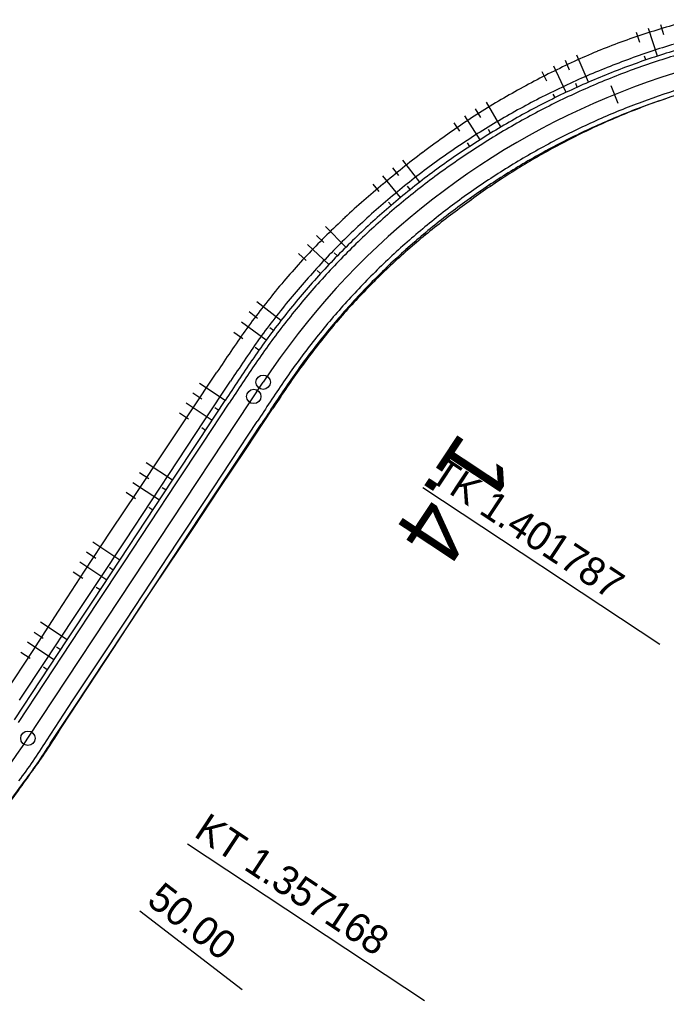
# Model space of a CAD drawing. Extents: x -481645 to -478728, y -1113199 to -1110710.
# Drawn here: x -478987.9 to -478920.3, y -1110817.8 to -1110715.2 of the extents above; entities that cross this region are included whole.
import ezdxf

# ---------------------------------------------------------------- set-up
doc = ezdxf.new("R2010")
doc.units = 0
for name, color, linetype in [('CP14_HATCH_SLOPE_L', 7, 'Continuous'), ('CP1_HECTOMETRY', 7, 'Continuous'), ('O6_HATCH_SLOPE_L', 7, 'Continuous'), ('O6_HATCH_SLOPE_R', 7, 'Continuous'), ('O6_HECTOMETRY', 7, 'Continuous'), ('O6_HLBODY', 7, 'Continuous'), ('O6_HRANA_TELESO', 7, 'Continuous'), ('O6_OSA', 7, 'Continuous'), ('O6_VOZOVKA', 7, 'Continuous'), ('O6_ZPEVKRAJ', 7, 'Continuous')]:
    doc.layers.add(name, color=color, linetype=linetype)

msp = doc.modelspace()

# ---------------------------------------------------------------- linework, layer by layer
at = {"layer": 'CP14_HATCH_SLOPE_L'}
for p, q in [((-478921.45, -1110723.87), (-478921.45, -1110723.88)), ((-478921.44, -1110723.89), (-478921.44, -1110723.89)), ((-478920.3, -1110723.48), (-478920.29, -1110723.49)), ((-478923.73, -1110724.71), (-478923.72, -1110724.73)), ((-478923.72, -1110724.74), (-478923.72, -1110724.74)), ((-478922.59, -1110724.28), (-478922.58, -1110724.3)), ((-478929.3, -1110727.12), (-478929.27, -1110727.19)), ((-478931.48, -1110728.2), (-478931.43, -1110728.29)), ((-478930.39, -1110727.65), (-478930.38, -1110727.69)), ((-478930.36, -1110727.73), (-478930.36, -1110727.73)), ((-478932.55, -1110728.77), (-478932.53, -1110728.82)), ((-478932.5, -1110728.86), (-478932.5, -1110728.86)), ((-478937.78, -1110731.85), (-478937.69, -1110731.99)), ((-478939.8, -1110733.2), (-478939.7, -1110733.36)), ((-478938.8, -1110732.52), (-478938.75, -1110732.59)), ((-478938.7, -1110732.67), (-478938.7, -1110732.67)), ((-478940.8, -1110733.9), (-478940.74, -1110733.98)), ((-478940.68, -1110734.06), (-478940.68, -1110734.06)), ((-478946.53, -1110738.4), (-478946.48, -1110738.46)), ((-478946.42, -1110738.53), (-478946.42, -1110738.53)), ((-478945.61, -1110737.61), (-478945.49, -1110737.75)), ((-478947.45, -1110739.2), (-478947.34, -1110739.32)), ((-478948.35, -1110740.01), (-478948.29, -1110740.07)), ((-478948.24, -1110740.13), (-478948.24, -1110740.13)), ((-478952.65, -1110744.29), (-478952.57, -1110744.37)), ((-478953.47, -1110745.19), (-478953.43, -1110745.23)), ((-478953.39, -1110745.27), (-478953.39, -1110745.27)), ((-478954.28, -1110746.1), (-478954.19, -1110746.17)), ((-478955.07, -1110747.02), (-478955.03, -1110747.06)), ((-478954.99, -1110747.09), (-478954.99, -1110747.09)), ((-478958.81, -1110751.81), (-478958.72, -1110751.87)), ((-478959.51, -1110752.8), (-478959.47, -1110752.83)), ((-478959.42, -1110752.86), (-478959.42, -1110752.86)), ((-478960.2, -1110753.8), (-478960.11, -1110753.86)), ((-478960.88, -1110754.82), (-478960.83, -1110754.85)), ((-478960.79, -1110754.88), (-478960.79, -1110754.88)), ((-478964.32, -1110760.04), (-478964.25, -1110760.09)), ((-478965.01, -1110761.08), (-478964.98, -1110761.11)), ((-478965.7, -1110762.12), (-478965.63, -1110762.17)), ((-478964.94, -1110761.13), (-478964.94, -1110761.13)), ((-478966.39, -1110763.17), (-478966.36, -1110763.19)), ((-478966.32, -1110763.21), (-478966.32, -1110763.21)), ((-478969.84, -1110768.38), (-478969.79, -1110768.42)), ((-478970.53, -1110769.43), (-478970.5, -1110769.44)), ((-478970.48, -1110769.45), (-478970.48, -1110769.45)), ((-478971.21, -1110770.47), (-478971.18, -1110770.49)), ((-478971.9, -1110771.51), (-478971.89, -1110771.52)), ((-478971.87, -1110771.53), (-478971.87, -1110771.53)), ((-478975.35, -1110776.73), (-478975.34, -1110776.73)), ((-478976.04, -1110777.77), (-478976.03, -1110777.77)), ((-478976.03, -1110777.77), (-478976.03, -1110777.77)), ((-478976.73, -1110778.81), (-478976.71, -1110778.82)), ((-478977.42, -1110779.85), (-478977.41, -1110779.86)), ((-478977.4, -1110779.86), (-478977.4, -1110779.86)), ((-478980.86, -1110785.07), (-478980.83, -1110785.09)), ((-478981.55, -1110786.11), (-478981.53, -1110786.12)), ((-478981.52, -1110786.13), (-478981.52, -1110786.13)), ((-478982.24, -1110787.16), (-478982.2, -1110787.18)), ((-478982.93, -1110788.2), (-478982.91, -1110788.21)), ((-478982.89, -1110788.22), (-478982.89, -1110788.22)), ((-478986.42, -1110793.44), (-478986.37, -1110793.47)), ((-478987.16, -1110794.49), (-478987.13, -1110794.5)), ((-478987.11, -1110794.52), (-478987.11, -1110794.52)), ((-478987.9, -1110795.52), (-478987.85, -1110795.56))]:
    msp.add_line(p, q, dxfattribs=at)
at = {"layer": 'CP1_HECTOMETRY'}
msp.add_line((-478987.06, -1110790.36), (-478962.46, -1110753.14), dxfattribs=at)
for centre, radius, start, end in [((-478895.71, -1110797.24), 80, 76.6017, 146.545), ((-479070.49, -1110735.23), 100, 317.0793, 326.545)]:
    msp.add_arc(centre, radius, start, end, dxfattribs=at)
at = {"layer": 'O6_HATCH_SLOPE_L'}
msp.add_circle((-478963.44, -1110754.63), 0.75, dxfattribs=at)
at = {"layer": 'O6_HATCH_SLOPE_R'}
for p, q in [((-478920.56, -1110716.84), (-478920.89, -1110715.79)), ((-478923.07, -1110717.64), (-478923.43, -1110716.58)), ((-478921.23, -1110719.05), (-478922.16, -1110716.18)), ((-478928.43, -1110721.78), (-478929.65, -1110718.97)), ((-478922.44, -1110719.45), (-478922.58, -1110719.07)), ((-478930.78, -1110722.84), (-478932.07, -1110720.09)), ((-478930.41, -1110720.53), (-478930.86, -1110719.52)), ((-478932.78, -1110721.66), (-478933.27, -1110720.68)), ((-478929.61, -1110722.3), (-478929.78, -1110721.92)), ((-478931.93, -1110723.39), (-478932.12, -1110723.02)), ((-478937.59, -1110726.45), (-478939.1, -1110723.88)), ((-478939.69, -1110725.48), (-478940.24, -1110724.58)), ((-478941.9, -1110726.89), (-478942.47, -1110726.02)), ((-478939.78, -1110727.79), (-478941.36, -1110725.29)), ((-478938.69, -1110727.11), (-478938.91, -1110726.74)), ((-478940.86, -1110728.49), (-478941.1, -1110728.12)), ((-478946.09, -1110732.22), (-478947.86, -1110729.92)), ((-478948.28, -1110731.53), (-478948.91, -1110730.74)), ((-478948.09, -1110733.82), (-478949.95, -1110731.58)), ((-478950.32, -1110733.2), (-478950.97, -1110732.43)), ((-478947.1, -1110733.01), (-478947.37, -1110732.66)), ((-478949.08, -1110734.65), (-478949.37, -1110734.31)), ((-478953.8, -1110739.01), (-478955.94, -1110736.86)), ((-478956.13, -1110738.54), (-478956.89, -1110737.79)), ((-478955.59, -1110740.85), (-478957.83, -1110738.74)), ((-478957.95, -1110740.43), (-478958.76, -1110739.7)), ((-478954.7, -1110739.92), (-478955.03, -1110739.6)), ((-478956.46, -1110741.79), (-478956.81, -1110741.48)), ((-478960.61, -1110746.7), (-478963.11, -1110744.75)), ((-478963.04, -1110746.48), (-478963.93, -1110745.8)), ((-478962.15, -1110748.75), (-478964.73, -1110746.87)), ((-478961.39, -1110747.72), (-478961.77, -1110747.44)), ((-478964.6, -1110748.6), (-478965.52, -1110747.95)), ((-478962.9, -1110749.8), (-478963.29, -1110749.52)), ((-478966.42, -1110755.05), (-478969.12, -1110753.26)), ((-478968.87, -1110754.93), (-478969.82, -1110754.3)), ((-478967.8, -1110757.14), (-478970.51, -1110755.34)), ((-478967.11, -1110756.09), (-478967.51, -1110755.82)), ((-478970.25, -1110757.01), (-478971.21, -1110756.38)), ((-478968.49, -1110758.18), (-478968.89, -1110757.91)), ((-478971.93, -1110763.39), (-478974.69, -1110761.57)), ((-478974.41, -1110763.25), (-478975.39, -1110762.61)), ((-478973.31, -1110765.48), (-478976.08, -1110763.65)), ((-478972.62, -1110764.44), (-478973.03, -1110764.17)), ((-478975.8, -1110765.33), (-478976.78, -1110764.68)), ((-478974, -1110766.52), (-478974.41, -1110766.25)), ((-478977.44, -1110771.74), (-478980.26, -1110769.87)), ((-478979.95, -1110771.58), (-478980.95, -1110770.92)), ((-478978.82, -1110773.82), (-478981.64, -1110771.96)), ((-478981.33, -1110773.66), (-478982.32, -1110773.01)), ((-478978.13, -1110772.78), (-478978.54, -1110772.51)), ((-478979.51, -1110774.86), (-478979.92, -1110774.59)), ((-478982.96, -1110780.08), (-478985.74, -1110778.24)), ((-478985.45, -1110779.93), (-478986.42, -1110779.29)), ((-478984.34, -1110782.16), (-478987.11, -1110780.33)), ((-478986.82, -1110782.02), (-478987.79, -1110781.38)), ((-478983.65, -1110781.12), (-478984.06, -1110780.85)), ((-478985.03, -1110783.21), (-478985.44, -1110782.93))]:
    msp.add_line(p, q, dxfattribs=at)
at = {"layer": 'O6_HECTOMETRY'}
for p, q in [((-478945.77, -1110764.16), (-478920.99, -1110780.53)), ((-478970.37, -1110801.39), (-478945.59, -1110817.76))]:
    msp.add_line(p, q, dxfattribs=at)
for centre in [(-478962.46, -1110753.14), (-478987.06, -1110790.36)]:
    msp.add_circle(centre, 0.75, dxfattribs=at)
at = {"layer": 'O6_HLBODY'}
for p, q in [((-478925.33, -1110724), (-478926.08, -1110722.15)), ((-478975.36, -1110808.39), (-478964.66, -1110816.62))]:
    msp.add_line(p, q, dxfattribs=at)
at = {"layer": 'O6_HRANA_TELESO'}
for p, q in [((-478968.63, -1110757.19), (-478965.88, -1110753.02)), ((-478971.39, -1110761.36), (-478968.63, -1110757.19)), ((-478974.15, -1110765.53), (-478971.39, -1110761.36)), ((-478976.9, -1110769.71), (-478974.15, -1110765.53)), ((-478979.66, -1110773.88), (-478976.9, -1110769.71)), ((-478982.42, -1110778.05), (-478979.66, -1110773.88)), ((-478985.17, -1110782.22), (-478982.42, -1110778.05)), ((-478987.93, -1110786.39), (-478985.17, -1110782.22))]:
    msp.add_line(p, q, dxfattribs=at)
for centre, radius, start, end in [((-478895.71, -1110797.24), 82.92, 104.8528, 108.4338), ((-478895.71, -1110797.24), 82.92, 108.4338, 112.0148), ((-478895.71, -1110797.24), 82.92, 112.0148, 115.5957), ((-478895.71, -1110797.24), 82.92, 115.5957, 119.1767), ((-478895.71, -1110797.24), 82.92, 119.1767, 122.7577), ((-478895.71, -1110797.24), 82.92, 122.7577, 126.3387), ((-478895.71, -1110797.24), 82.92, 126.3387, 129.9197), ((-478895.71, -1110797.24), 82.92, 129.9197, 133.5007), ((-478895.71, -1110797.24), 82.92, 133.5007, 137.0817), ((-478895.71, -1110797.24), 82.92, 137.0817, 140.6626), ((-478895.71, -1110797.24), 82.92, 140.6626, 144.2436), ((-478758.72, -1110890.73), 248.75, 145.2068, 146.3854)]:
    msp.add_arc(centre, radius, start, end, dxfattribs=at)
at = {"layer": 'O6_OSA'}
for p, q in [((-478970.06, -1110756.25), (-478967.29, -1110752.08)), ((-478964.25, -1110760.09), (-478961.48, -1110755.92)), ((-478972.84, -1110760.41), (-478970.06, -1110756.25)), ((-478967.02, -1110764.25), (-478964.25, -1110760.09)), ((-478975.61, -1110764.56), (-478972.84, -1110760.41)), ((-478978.39, -1110768.72), (-478975.61, -1110764.56)), ((-478969.79, -1110768.42), (-478967.02, -1110764.25)), ((-478981.15, -1110772.89), (-478978.39, -1110768.72)), ((-478972.57, -1110772.57), (-478969.79, -1110768.42)), ((-478983.87, -1110777.09), (-478981.15, -1110772.89)), ((-478975.34, -1110776.73), (-478972.57, -1110772.57)), ((-478986.59, -1110781.28), (-478983.87, -1110777.09)), ((-478978.09, -1110780.91), (-478975.34, -1110776.73)), ((-478989.32, -1110785.48), (-478986.59, -1110781.28)), ((-478980.83, -1110785.09), (-478978.09, -1110780.91)), ((-478983.58, -1110789.27), (-478980.83, -1110785.09))]:
    msp.add_line(p, q, dxfattribs=at)
for centre, radius, start, end in [((-478896.21, -1110797.39), 84.85, 104.504, 108.0851), ((-478895.81, -1110797.27), 84.87, 108.3674, 111.9484), ((-478894.52, -1110796.7), 84.83, 112.897, 116.4784), ((-478894.53, -1110796.61), 84.75, 116.5022, 120.0836), ((-478894.54, -1110796.52), 84.67, 120.1042, 123.6856), ((-478895.32, -1110797.09), 77.73, 108.7397, 112.3208), ((-478895.17, -1110797), 77.7, 112.4513, 116.0324), ((-478894.55, -1110796.43), 84.58, 123.7165, 127.298), ((-478895.07, -1110796.9), 77.65, 116.1284, 119.7096), ((-478894.99, -1110796.67), 84.51, 126.9602, 130.5414), ((-478895.07, -1110796.85), 77.61, 119.73, 123.3111), ((-478895.07, -1110796.79), 77.56, 123.3359, 126.917), ((-478896.37, -1110797.82), 84.51, 129.3279, 132.9091), ((-478896.14, -1110797.57), 77.55, 125.9385, 129.5196), ((-478896.39, -1110797.92), 84.56, 132.8479, 136.4291), ((-478896.11, -1110797.59), 77.59, 129.5275, 133.1086), ((-478895.92, -1110797.47), 84.6, 136.8741, 140.4551), ((-478896.08, -1110797.6), 77.62, 133.1216, 136.7027), ((-478895.76, -1110797.3), 84.61, 140.6128, 144.1938), ((-478895.8, -1110797.33), 77.64, 136.9881, 140.5691), ((-478755.88, -1110892.6), 253.85, 145.2193, 146.3896), ((-478895.71, -1110797.24), 77.64, 140.666, 144.247), ((-478767.54, -1110884.93), 232.93, 145.1618, 146.3683), ((-479027.52, -1110763.08), 51.15, 323.5502, 329.2088), ((-479070.67, -1110735.48), 102.31, 322.6103, 325.4751)]:
    msp.add_arc(centre, radius, start, end, dxfattribs=at)
at = {"layer": 'O6_VOZOVKA'}
for p, q in [((-478968.76, -1110759.5), (-478966, -1110755.32)), ((-478965.84, -1110761.43), (-478963.08, -1110757.25)), ((-478971.51, -1110763.67), (-478968.76, -1110759.5)), ((-478968.59, -1110765.6), (-478965.84, -1110761.43)), ((-478974.27, -1110767.84), (-478971.51, -1110763.67)), ((-478971.35, -1110769.77), (-478968.59, -1110765.6)), ((-478977.03, -1110772.01), (-478974.27, -1110767.84)), ((-478974.11, -1110773.94), (-478971.35, -1110769.77)), ((-478979.78, -1110776.18), (-478977.03, -1110772.01)), ((-478976.86, -1110778.11), (-478974.11, -1110773.94)), ((-478982.54, -1110780.35), (-478979.78, -1110776.18)), ((-478979.62, -1110782.28), (-478976.86, -1110778.11)), ((-478985.3, -1110784.53), (-478982.54, -1110780.35)), ((-478982.38, -1110786.46), (-478979.62, -1110782.28)), ((-478988.05, -1110788.7), (-478985.3, -1110784.53)), ((-478985.13, -1110790.63), (-478982.38, -1110786.46))]:
    msp.add_line(p, q, dxfattribs=at)
for centre, radius, start, end in [((-478895.71, -1110797.24), 81.75, 106.2794, 109.8604), ((-478895.71, -1110797.24), 81.75, 109.8604, 113.4414), ((-478895.71, -1110797.24), 78.25, 106.2794, 109.8604), ((-478895.71, -1110797.24), 81.75, 113.4414, 117.0224), ((-478895.71, -1110797.24), 78.25, 109.8604, 113.4414), ((-478895.71, -1110797.24), 81.75, 117.0224, 120.6034), ((-478895.71, -1110797.24), 78.25, 113.4414, 117.0224), ((-478895.71, -1110797.24), 81.75, 120.6034, 124.1843), ((-478895.71, -1110797.24), 78.25, 117.0224, 120.6034), ((-478895.71, -1110797.24), 81.75, 124.1843, 127.7653), ((-478895.71, -1110797.24), 78.25, 120.6034, 124.1843), ((-478895.71, -1110797.24), 81.75, 127.7653, 131.3463), ((-478895.71, -1110797.24), 78.25, 124.1843, 127.7653), ((-478895.71, -1110797.24), 78.25, 127.7653, 131.3463), ((-478895.71, -1110797.24), 81.75, 131.3463, 134.9273), ((-478895.71, -1110797.24), 78.25, 131.3463, 134.9273), ((-478895.71, -1110797.24), 81.75, 134.9273, 138.5083), ((-478895.71, -1110797.24), 78.25, 134.9273, 138.5083), ((-478895.71, -1110797.24), 81.75, 138.5083, 142.0893), ((-478895.71, -1110797.24), 78.25, 138.5083, 142.0893), ((-478895.71, -1110797.24), 81.75, 142.0893, 145.6703), ((-478895.71, -1110797.24), 78.25, 142.0893, 145.6703), ((-478760.26, -1110888.81), 245.25, 145.8492, 147.0236), ((-478766.1, -1110884.95), 234.75, 145.833, 147.0468), ((-479028.47, -1110763.97), 50.88, 322.693, 328.4079)]:
    msp.add_arc(centre, radius, start, end, dxfattribs=at)
at = {"layer": 'O6_ZPEVKRAJ'}
for p, q in [((-478969.17, -1110759.22), (-478966.42, -1110755.05)), ((-478965.42, -1110761.7), (-478962.66, -1110757.53)), ((-478971.93, -1110763.39), (-478969.17, -1110759.22)), ((-478968.18, -1110765.87), (-478965.42, -1110761.7)), ((-478974.69, -1110767.56), (-478971.93, -1110763.39)), ((-478970.93, -1110770.04), (-478968.18, -1110765.87)), ((-478977.44, -1110771.74), (-478974.69, -1110767.56)), ((-478973.69, -1110774.22), (-478970.93, -1110770.04)), ((-478980.2, -1110775.91), (-478977.44, -1110771.74)), ((-478976.45, -1110778.39), (-478973.69, -1110774.22)), ((-478982.96, -1110780.08), (-478980.2, -1110775.91)), ((-478979.2, -1110782.56), (-478976.45, -1110778.39)), ((-478985.71, -1110784.25), (-478982.96, -1110780.08)), ((-478981.96, -1110786.73), (-478979.2, -1110782.56)), ((-478988.47, -1110788.42), (-478985.71, -1110784.25)), ((-478984.72, -1110790.9), (-478981.96, -1110786.73))]:
    msp.add_line(p, q, dxfattribs=at)
for centre, radius, start, end in [((-478895.71, -1110797.24), 82.25, 106.2794, 109.8604), ((-478895.71, -1110797.24), 82.25, 109.8604, 113.4414), ((-478895.71, -1110797.24), 82.25, 113.4414, 117.0224), ((-478895.71, -1110797.24), 77.75, 106.2794, 109.8604), ((-478895.71, -1110797.24), 82.25, 117.0224, 120.6034), ((-478895.71, -1110797.24), 77.75, 109.8604, 113.4414), ((-478895.71, -1110797.24), 77.75, 113.4414, 117.0224), ((-478895.71, -1110797.24), 82.25, 120.6034, 124.1843), ((-478895.71, -1110797.24), 77.75, 117.0224, 120.6034), ((-478895.71, -1110797.24), 82.25, 124.1843, 127.7653), ((-478895.71, -1110797.24), 77.75, 120.6034, 124.1843), ((-478895.71, -1110797.24), 82.25, 127.7653, 131.3463), ((-478895.71, -1110797.24), 77.75, 124.1843, 127.7653), ((-478895.71, -1110797.24), 82.25, 131.3463, 134.9273), ((-478895.71, -1110797.24), 77.75, 127.7653, 131.3463), ((-478895.71, -1110797.24), 82.25, 134.9273, 138.5083), ((-478895.71, -1110797.24), 77.75, 131.3463, 134.9273), ((-478895.71, -1110797.24), 77.75, 134.9273, 138.5083), ((-478895.71, -1110797.24), 82.25, 138.5083, 142.0893), ((-478895.71, -1110797.24), 77.75, 138.5083, 142.0893), ((-478895.71, -1110797.24), 82.25, 142.0893, 145.6703), ((-478895.71, -1110797.24), 77.75, 142.0893, 145.6703), ((-478759.43, -1110889.36), 246.75, 145.8514, 147.0204), ((-478766.93, -1110884.39), 233.25, 145.8305, 147.0503), ((-479028.26, -1110764.12), 51.12, 322.6945, 328.4048), ((-479070.49, -1110735.23), 102.25, 321.2966, 324.1614)]:
    msp.add_arc(centre, radius, start, end, dxfattribs=at)

# ---------------------------------------------------------------- texts
at = {"layer": 'O6_HATCH_SLOPE_L'}
msp.add_text('1.4', height=6.999, rotation=236.4993, dxfattribs=at).set_placement((-478941.77, -1110758.11))
at = {"layer": 'O6_HECTOMETRY'}
for s, p in [('TK 1.401787', (-478945.22, -1110763.33)), ('KT 1.357168', (-478969.82, -1110800.55))]:
    msp.add_text(s, height=2.999, rotation=326.545, dxfattribs=at).set_placement(p)
at = {"layer": 'O6_HLBODY'}
msp.add_text('50.00', height=3, rotation=322.4379, dxfattribs=at).set_placement((-478974.76, -1110807.6))

doc.saveas('drawing.dxf')
